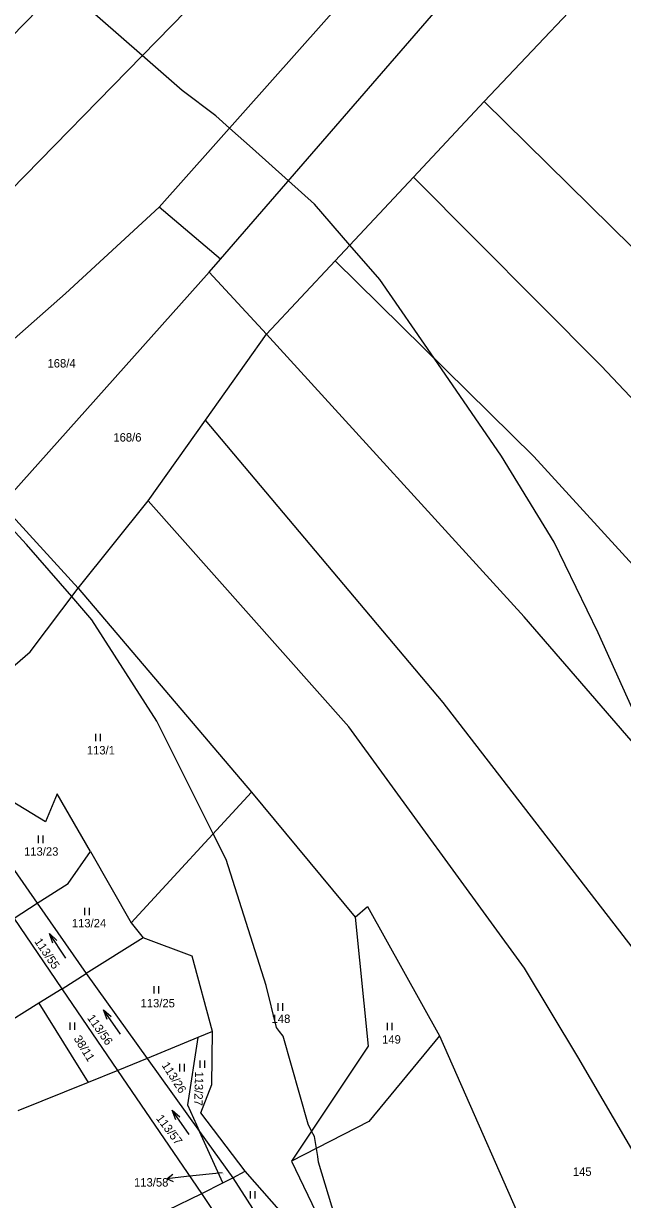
# Model space of a CAD drawing. Extents: x -749173 to -746119, y -1132678 to -1130338.
# Drawn here: x -747491.9 to -747370.7, y -1131098.8 to -1130860.8 of the extents above; entities that cross this region are included whole.
import ezdxf

# ---------------------------------------------------------------- set-up
doc = ezdxf.new("R2010")
doc.units = 0
for name, color, linetype in [('Vrstva 1', 7, 'Continuous'), ('Vrstva 16', 7, 'Continuous'), ('Vrstva 18', 7, 'Continuous'), ('Vrstva 25', 7, 'Continuous'), ('Vrstva 52', 7, 'Continuous'), ('Vrstva 6', 7, 'Continuous')]:
    doc.layers.add(name, color=color, linetype=linetype)

msp = doc.modelspace()

# ---------------------------------------------------------------- linework, layer by layer
at = {"layer": 'Vrstva 1'}
for points in [[(-747496.26, -1130958.17), (-747480.85, -1130975.08)], [(-747480.85, -1130975.08), (-747445.77, -1131016.39)], [(-747505.21, -1131015.73), (-747489.11, -1131038.86)], [(-747445.77, -1131016.39), (-747424.82, -1131041.7)], [(-747489.11, -1131038.86), (-747479.21, -1131053.09)], [(-747424.82, -1131041.7), (-747422.32, -1131039.54)], [(-747422.32, -1131039.54), (-747407.71, -1131065.71)], [(-747484.08, -1131056.18), (-747493.76, -1131041.86)], [(-747479.21, -1131053.09), (-747466.89, -1131070.28)], [(-747472.77, -1131072.73), (-747484.08, -1131056.18)], [(-747407.71, -1131065.71), (-747387.68, -1131111.18)], [(-747466.89, -1131070.28), (-747456.29, -1131085.07)], [(-747455.83, -1131097.63), (-747472.77, -1131072.73)], [(-747456.29, -1131085.07), (-747449.55, -1131094.47)], [(-747449.55, -1131094.47), (-747440.84, -1131108.03)], [(-747446.81, -1131111.05), (-747455.83, -1131097.63)]]:
    msp.add_lwpolyline(points, dxfattribs=at)
at = {"layer": 'Vrstva 16'}
msp.add_line((-747461.53, -1131095.23), (-747462.91, -1131094.63), dxfattribs=at)
for points in [[(-747458.93, -1131094.2), (-747462.91, -1131094.63), (-747461.69, -1131093.74)], [(-747451.68, -1131093.42), (-747458.93, -1131094.2)]]:
    msp.add_lwpolyline(points, dxfattribs=at)
at = {"layer": 'Vrstva 25'}
for p, q in [((-747477.29, -1131004.55), (-747477.29, -1131006.05)), ((-747476.29, -1131006.05), (-747476.29, -1131004.55)), ((-747488.93, -1131025.18), (-747488.93, -1131026.68)), ((-747487.93, -1131026.68), (-747487.93, -1131025.18)), ((-747479.53, -1131039.81), (-747479.53, -1131041.31)), ((-747478.53, -1131041.31), (-747478.53, -1131039.81)), ((-747483.31, -1131050.02), (-747486.63, -1131045.02)), ((-747465.53, -1131055.63), (-747465.53, -1131057.13)), ((-747464.53, -1131057.13), (-747464.53, -1131055.63)), ((-747472.24, -1131065.38), (-747475.7, -1131060.48)), ((-747440.45, -1131059.13), (-747440.45, -1131060.63)), ((-747439.45, -1131060.63), (-747439.45, -1131059.13)), ((-747482.53, -1131062.99), (-747482.53, -1131064.49)), ((-747481.53, -1131064.49), (-747481.53, -1131062.99)), ((-747418.33, -1131063.08), (-747418.33, -1131064.58)), ((-747417.33, -1131064.58), (-747417.33, -1131063.08)), ((-747460.33, -1131071.41), (-747460.33, -1131072.91)), ((-747459.33, -1131072.91), (-747459.33, -1131071.41)), ((-747456.22, -1131070.7), (-747456.22, -1131072.2)), ((-747455.22, -1131072.2), (-747455.22, -1131070.7)), ((-747458.34, -1131085.66), (-747461.8, -1131080.76)), ((-747446.03, -1131097.15), (-747446.03, -1131098.65)), ((-747445.03, -1131098.65), (-747445.03, -1131097.15))]:
    msp.add_line(p, q, dxfattribs=at)
for points in [[(-747485.94, -1131046.96), (-747486.63, -1131045.02), (-747485.11, -1131046.41)], [(-747474.96, -1131062.4), (-747475.7, -1131060.48), (-747474.14, -1131061.82)], [(-747461.06, -1131082.68), (-747461.8, -1131080.76), (-747460.24, -1131082.1)]]:
    msp.add_lwpolyline(points, dxfattribs=at)
at = {"layer": 'Vrstva 52'}
for points in [[(-747367.19, -1131002.84), (-747375.62, -1130984.12), (-747384.56, -1130965.75), (-747395.19, -1130948.37), (-747408.83, -1130928.56), (-747419.81, -1130912.62), (-747425.85, -1130905.64), (-747433, -1130897.37), (-747435.68, -1130894.98), (-747438.29, -1130892.65), (-747445.58, -1130886.13), (-747450.21, -1130881.99), (-747453, -1130879.5), (-747459.81, -1130874.37), (-747467.9, -1130867.28), (-747480.62, -1130856.12)], [(-747424.79, -1131115.8), (-747432.19, -1131091.25), (-747432.36, -1131090.14), (-747432.62, -1131088.49), (-747433, -1131086.12), (-747433.6, -1131084.98), (-747434.31, -1131083.62), (-747439.37, -1131065.75), (-747440.07, -1131064.82), (-747440.69, -1131064), (-747442.81, -1131055.5), (-747450.87, -1131030), (-747453.49, -1131024.79), (-747464.94, -1131002), (-747478.06, -1130981.5), (-747482.13, -1130976.79), (-747491.25, -1130966.25), (-747497.5, -1130959.57)]]:
    msp.add_lwpolyline(points, dxfattribs=at)
at = {"layer": 'Vrstva 6'}
for points in [[(-747442.58, -1130810.47), (-747503.21, -1130872.55)], [(-747452.04, -1130908.53), (-747389.53, -1130836.33)], [(-747464.43, -1130898), (-747419.65, -1130847.56)], [(-747370.72, -1130846.96), (-747398.68, -1130876.61)], [(-747453.02, -1130852.06), (-747509.43, -1130909.76)], [(-747398.68, -1130876.61), (-747412.97, -1130891.88)], [(-747368.77, -1130906.07), (-747398.68, -1130876.61)], [(-747412.97, -1130891.88), (-747428.85, -1130908.85)], [(-747375, -1130930.12), (-747412.97, -1130891.88)], [(-747483.39, -1130915.42), (-747464.43, -1130898)], [(-747452.04, -1130908.53), (-747464.43, -1130898)], [(-747454.36, -1130911.13), (-747452.04, -1130908.53)], [(-747496.26, -1130958.17), (-747454.36, -1130911.13)], [(-747442.73, -1130923.69), (-747454.36, -1130911.13)], [(-747428.85, -1130908.85), (-747442.73, -1130923.69)], [(-747428.85, -1130908.85), (-747388.68, -1130948.41)], [(-747497.88, -1130928.23), (-747483.39, -1130915.42)], [(-747455.08, -1130941.09), (-747442.73, -1130923.69)], [(-747390.58, -1130980.92), (-747442.73, -1130923.69)], [(-747315.73, -1130992.85), (-747375, -1130930.12)], [(-747466.65, -1130957.41), (-747455.08, -1130941.09)], [(-747407, -1130998.24), (-747455.08, -1130941.09)], [(-747388.68, -1130948.41), (-747322.17, -1131021.26)], [(-747480.85, -1130975.08), (-747466.65, -1130957.41)], [(-747426.05, -1131003.14), (-747466.65, -1130957.41)], [(-747490.53, -1130988), (-747480.85, -1130975.08)], [(-747354.26, -1131022.92), (-747390.58, -1130980.92)], [(-747511.77, -1131006.31), (-747490.53, -1130988)], [(-747346.3, -1131076.82), (-747407, -1130998.24)], [(-747390.52, -1131051.98), (-747426.05, -1131003.14)], [(-747487.41, -1131022.36), (-747504.08, -1131012.3)], [(-747485.06, -1131016.72), (-747487.41, -1131022.36)], [(-747478.31, -1131028.41), (-747485.06, -1131016.72)], [(-747470.12, -1131042.87), (-747445.77, -1131016.39)], [(-747482.82, -1131034.88), (-747478.31, -1131028.41)], [(-747478.31, -1131028.41), (-747470.12, -1131042.87)], [(-747489.11, -1131038.86), (-747482.82, -1131034.88)], [(-747493.76, -1131041.86), (-747489.11, -1131038.86)], [(-747424.82, -1131041.7), (-747422.19, -1131067.82)], [(-747470.12, -1131042.87), (-747467.67, -1131045.88)], [(-747467.67, -1131045.88), (-747479.21, -1131053.09)], [(-747457.76, -1131049.58), (-747467.67, -1131045.88)], [(-747453.62, -1131064.84), (-747457.76, -1131049.58)], [(-747484.08, -1131056.18), (-747479.21, -1131053.09)], [(-747379.77, -1131069.99), (-747390.52, -1131051.98)], [(-747484.08, -1131056.18), (-747488.78, -1131059.1)], [(-747488.78, -1131059.1), (-747497.04, -1131064.23)], [(-747488.78, -1131059.1), (-747478.83, -1131075.18)], [(-747453.62, -1131064.84), (-747456.65, -1131066.03)], [(-747453.76, -1131075.58), (-747453.62, -1131064.84)], [(-747407.71, -1131065.71), (-747422, -1131083.03)], [(-747456.65, -1131066.03), (-747466.89, -1131070.28)], [(-747456.65, -1131066.03), (-747458.74, -1131079.69)], [(-747422.19, -1131067.82), (-747437.65, -1131091.07)], [(-747466.89, -1131070.28), (-747472.77, -1131072.73)], [(-747357.62, -1131107.84), (-747379.77, -1131069.99)], [(-747472.77, -1131072.73), (-747478.83, -1131075.18)], [(-747478.83, -1131075.18), (-747493.05, -1131080.92)], [(-747456, -1131081.28), (-747453.76, -1131075.58)], [(-747458.74, -1131079.69), (-747456.29, -1131085.07)], [(-747447.06, -1131093.1), (-747456, -1131081.28)], [(-747422, -1131083.03), (-747437.65, -1131091.07)], [(-747451.56, -1131095.48), (-747456.29, -1131085.07)], [(-747437.65, -1131091.07), (-747431.95, -1131103.02)], [(-747449.55, -1131094.47), (-747447.06, -1131093.1)], [(-747436.27, -1131105.41), (-747447.06, -1131093.1)], [(-747455.83, -1131097.63), (-747451.56, -1131095.48)], [(-747451.56, -1131095.48), (-747449.55, -1131094.47)], [(-747462.74, -1131101.03), (-747455.83, -1131097.63)]]:
    msp.add_lwpolyline(points, dxfattribs=at)

# ---------------------------------------------------------------- texts
at = {"layer": 'Vrstva 16'}
msp.add_text('113/58', height=1.7, dxfattribs=at).set_placement((-747469.53, -1131096.22))
at = {"layer": 'Vrstva 18'}
for s, p in [('168/4', (-747487.03, -1130930.43)), ('168/6', (-747473.71, -1130945.42)), ('113/1', (-747479.08, -1131008.75)), ('113/23', (-747491.78, -1131029.25)), ('113/24', (-747482.11, -1131043.76)), ('113/25', (-747468.21, -1131059.95)), ('148', (-747441.7, -1131063.1)), ('149', (-747419.35, -1131067.28)), ('145', (-747380.76, -1131094.05))]:
    msp.add_text(s, height=1.7, dxfattribs=at).set_placement(p)
for s, height, rotation, p in [('113/55', 1.7, 304.1788, (-747489.76, -1131046.63)), ('113/56', 1.7, 305.1807, (-747479.09, -1131062.11)), ('38/11', 1.7, 301.6948, (-747481.8, -1131066.25)), ('113/26', 1.7, 302.5112, (-747464, -1131071.66)), ('113/27', 1.7, 268.3508, (-747457.17, -1131072.9)), ('113/57', 1.7, 307.0357, (-747465.16, -1131082.44)), ('113/58', 0.1, 295.0836, (-747451.68, -1131093.42))]:
    msp.add_text(s, height=height, rotation=rotation, dxfattribs=at).set_placement(p)

doc.saveas('drawing.dxf')
